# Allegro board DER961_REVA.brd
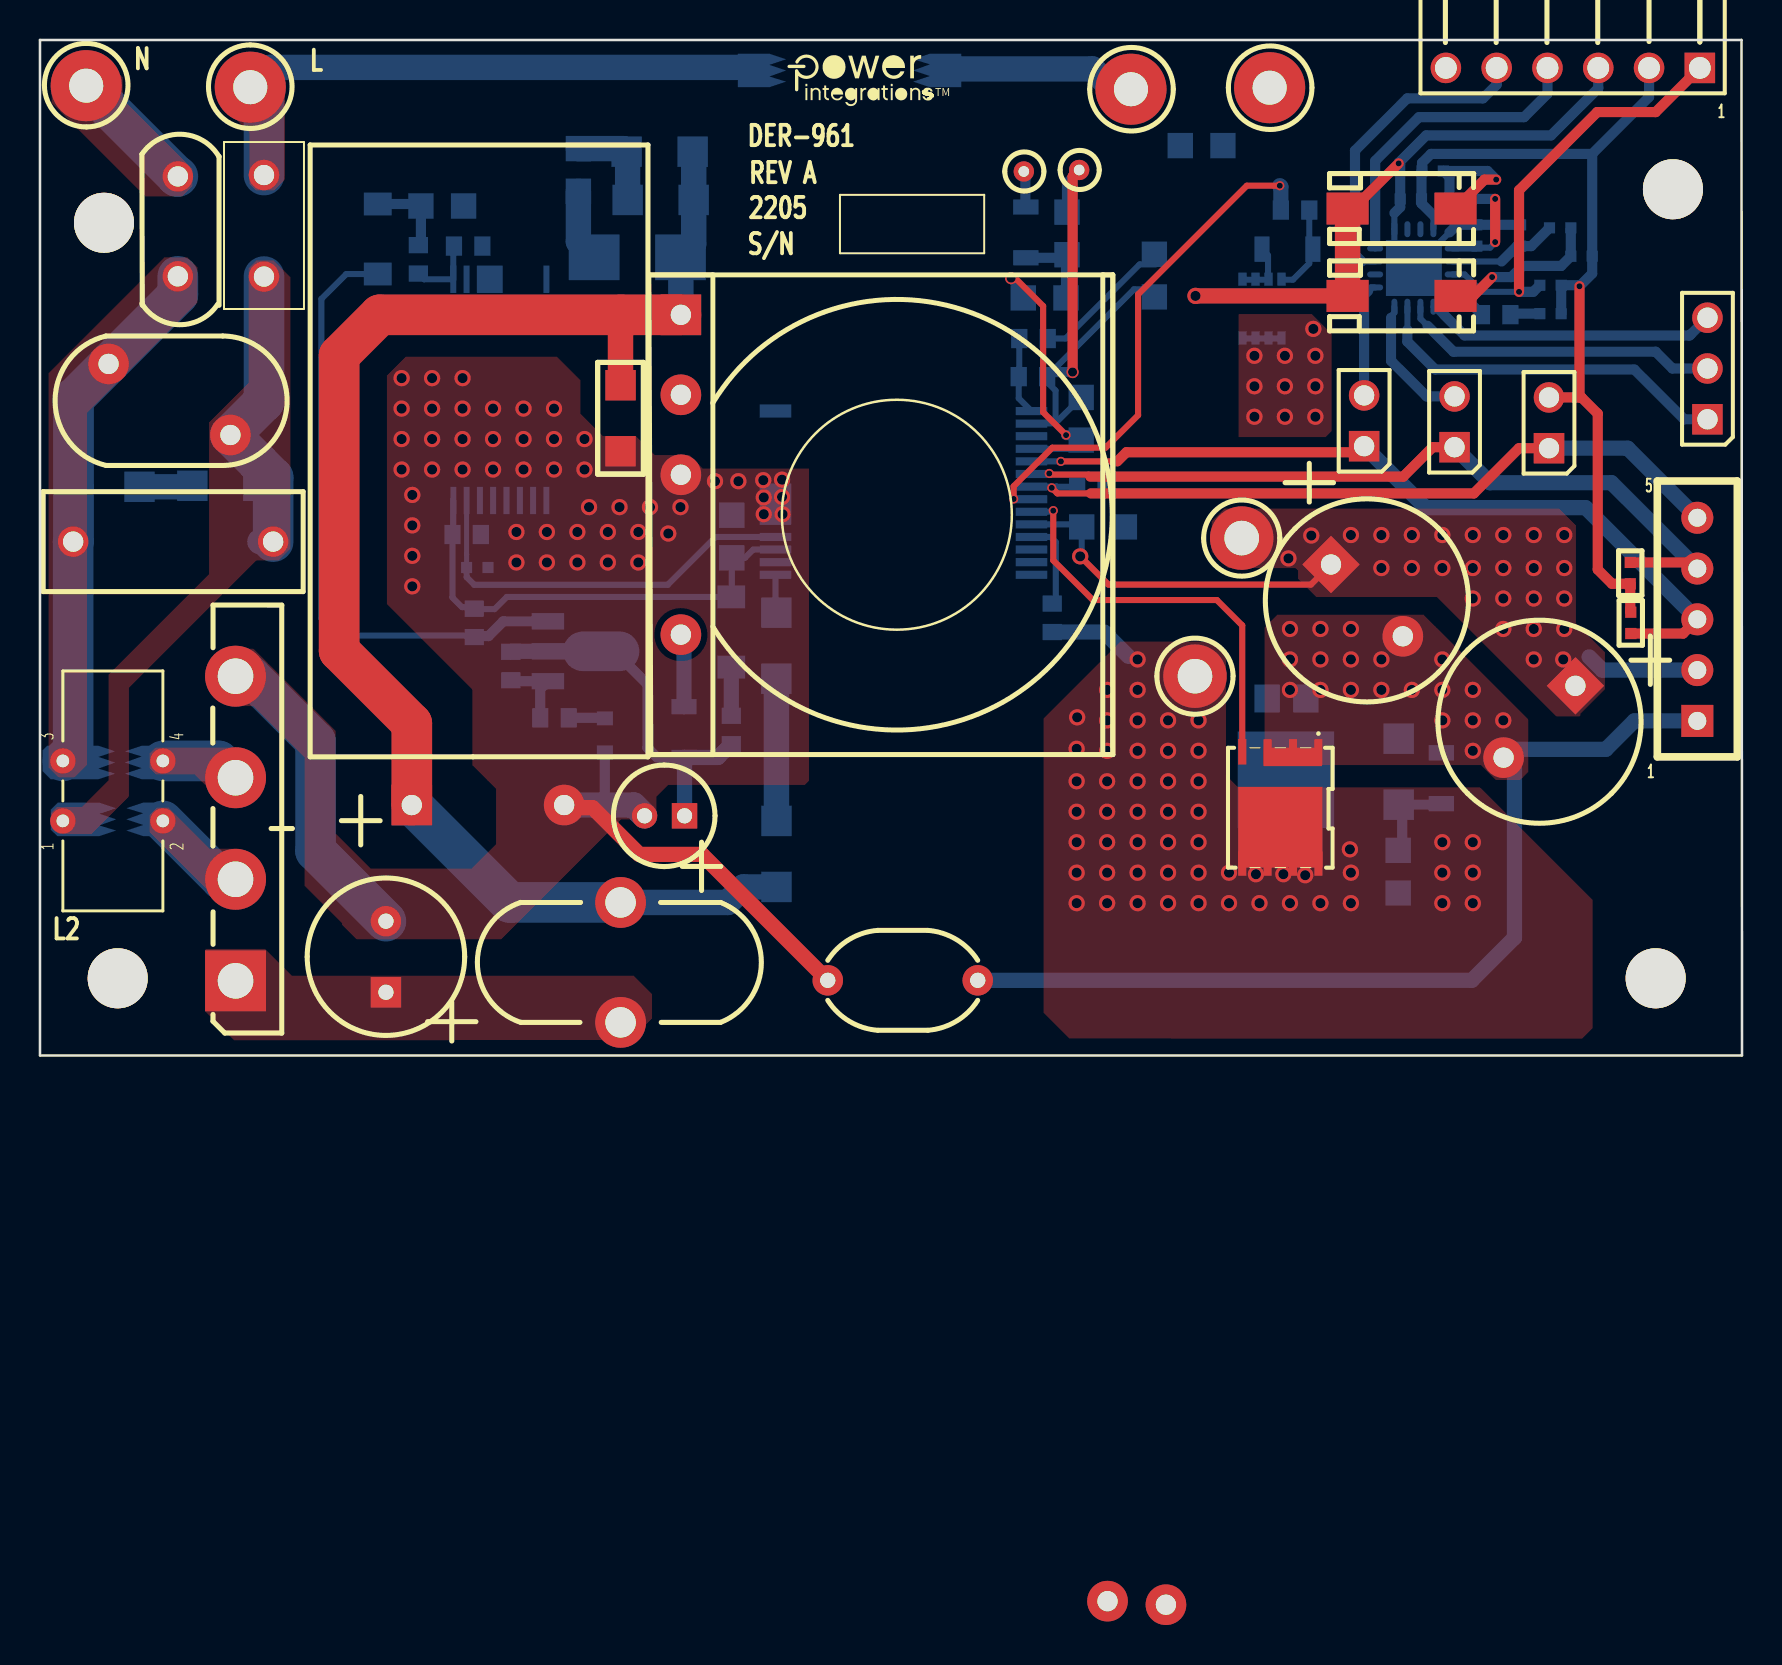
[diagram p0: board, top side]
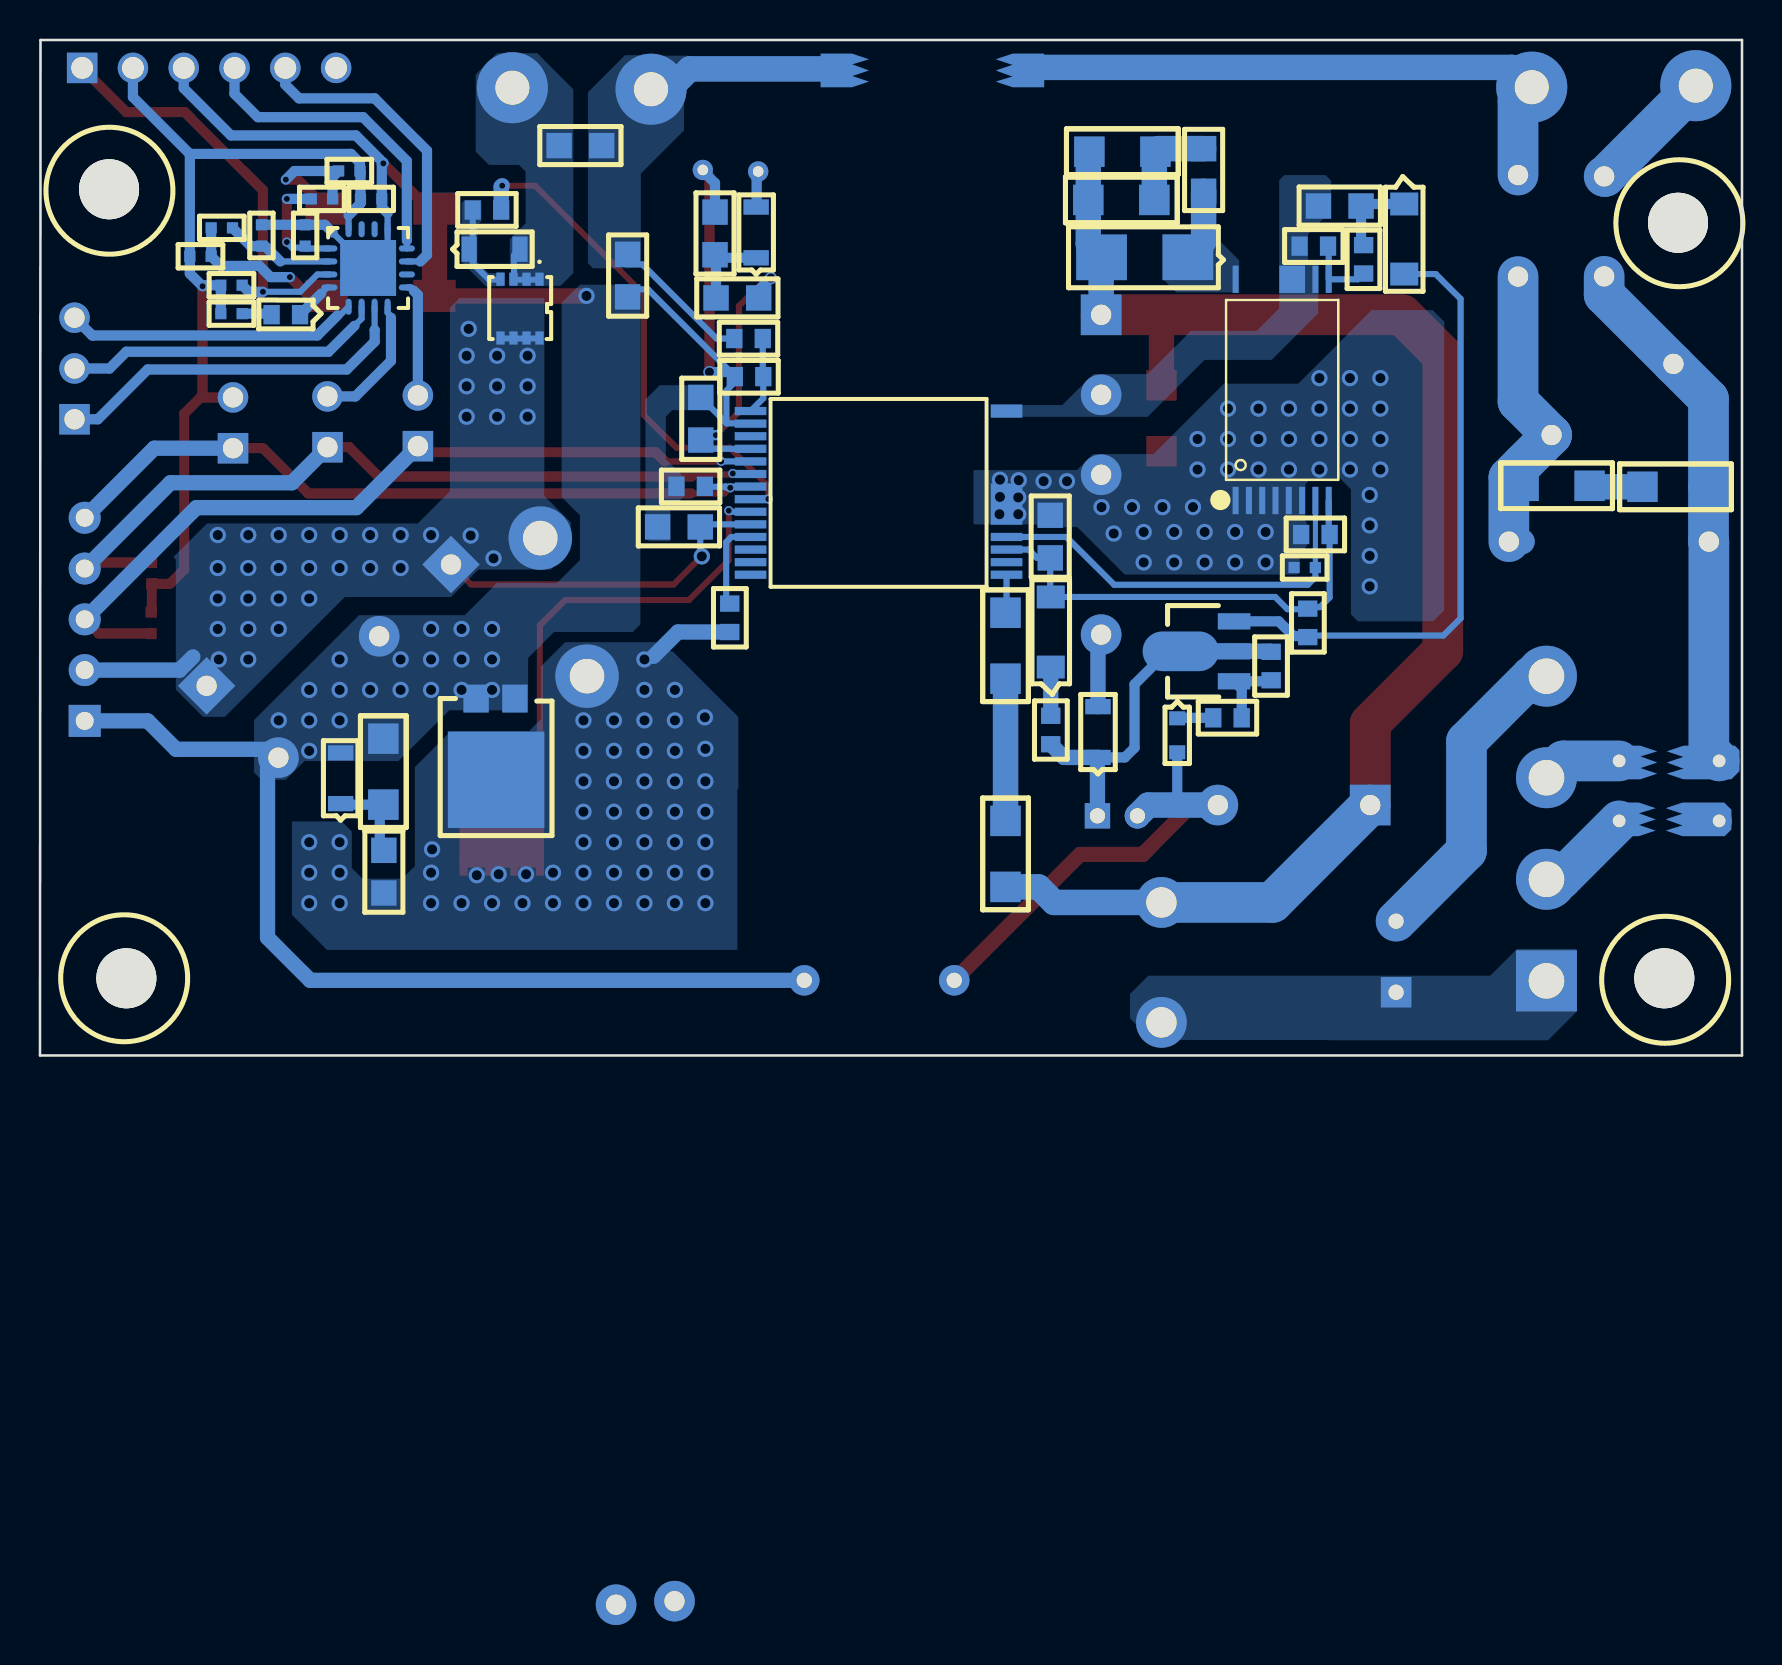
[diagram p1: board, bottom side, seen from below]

Outline 85.12 x 50.8 mm; copper layers: TOP, BOTTOM. Coordinates in mm from the lower left corner of the outline.
Outline path: 0,50.8 0,0 85.12,0 85.09,50.8 0,50.8

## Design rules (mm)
constraint set DEFAULT: min track width 0.508

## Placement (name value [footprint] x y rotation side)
BR1  GBU4K-BP  [PIDAXBRIDGEGBU8]  9.78 3.73 90 top
C1  470 pF  [PINPCAPRAD7P5X11P5LS7P5MM030]  39.4 3.76 0 top
C2  100 nF  [PISMC1206]  32.69 42.8 180 bottom
C3  22 uF  [PIPOLCAPCLYD320LS140030]  17.3 3.16 90 top
C4  100 uF  [PIPOLCAPCLYD630LS300040]  18.59 12.53 0 bottom
C5  2.2 nF  [PISMC1206]  29.03 33.53 270 top
C6  470 uF  [PIPOLCAPCYLD400LS200040]  76.78 18.49 225 top
C7  470 uF  [PIPOLCAPCYLD400LS200040]  64.56 24.56 315 top
C8  1 uF  [PISMC0805]  57.02 45.52 0 bottom
C9  680 pf  [PISMC0805]  67.92 8.13 90 bottom
C10  4.7uF  [PISMC0603]  50.37 33.96 180 bottom
C11  2.2 uF  [PISMC0805]  52.07 30.78 90 bottom
C12  10 uF  [PISMC0805]  51.36 42.19 270 bottom
C13  2.2 uF  [PISMC0805]  54.23 26.44 180 bottom
C14  22 uF  [PIPOLCAPCLYD200LS80030]  32.23 11.99 180 top
C15  2.2 uF  [PISMC0603]  53.29 28.47 180 bottom
C16  100 nF  [PISMC0603]  20.7 40.49 0 bottom
C17  1 uF  [PISMC0805]  21.18 42.49 180 bottom
C18  0.1 uF  [PINPXCAPRAD5X13X11P1MM040]  11.66 25.7 180 top
C19  100 nF  [PISMC0603]  20.62 26.06 0 bottom
C20  0.47 uF  [PISMC0805]  34.59 24.89 90 bottom
C21  1 nF  [PISMR0402]  71.86 40.49 90 bottom
C22  100 nF  [PISMR0402]  68.02 42.85 0 bottom
C23  1 nF  [PISMR0402]  74.04 40.49 90 bottom
C24  100 nF  [PISMC1206]  32.64 45.21 180 bottom
D1  BAV19WS  [PISMSOD323]  63.65 40.34 180 bottom
D2  BAV19WS  [PISMSOD323]  70.08 12.6 90 bottom
D3  V12P12-M3/86A  [PI_SM_D_TO-277A]  63.32 17.86 0 bottom
D4  BAV3004WS-7  [PISMSOD323]  32.21 14.91 90 bottom
D5  BAV19WS  [PISMSOD323]  49.3 39.9 90 bottom
D6  HS1KFL  [PI_SM_SOD-123_12]  16.89 42.6 270 bottom
D7  Green  [PI_SM_D_0603]  72.11 37.06 0 bottom
F1  3.15 A  [PI_RST_MICROFUSE]  11.2 44.04 270 top
FL1  Hole_70mils  [PI_HOLE_70MIL]  60.12 25.88 90 top
FL2  Hole_70mils  [PI_HOLE_70MIL]  57.78 18.97 90 top
FL3  Hole_30mils  [PI_HOLE_30MIL]  49.2 44.22 90 top
FL4  Hole_30mils  [PI_HOLE_30MIL]  51.97 44.3 90 top
J1  CON6  [PI_MOLEX_06_RA_22SERIES]  83.01 49.4 180 bottom
J2  CON2  [PIMOLEX2KKHEADER]  66.22 30.48 90 top
J3  CON5  [PI_HDRF_1X5_HIROSE]  82.88 16.74 90 top
J4  CON2  [PIMOLEX2KKHEADER]  75.46 30.38 90 top
J5  CON3  [PI_MOLEX_3_100_HEADER]  83.39 31.83 90 top
J6  CON2  [PIMOLEX2KKHEADER]  70.74 30.43 90 top
L1  68 uH  [PI2P14DX6MMWD060]  29.03 1.66 90 top
L2  250 uH  [PI_TOROID_CMC4P_V_275UH]  1.14 11.73 90 top
MTG_HOLE1  No 4  [PIMTGHOLE4]  81.66 43.33 0 top
MTG_HOLE2  No 4  [PIMTGHOLE4]  3.89 3.86 0 top
MTG_HOLE3  No 4  [PIMTGHOLE4]  80.8 3.86 0 top
MTG_HOLE4  No 4  [PIMTGHOLE4]  3.2 41.66 0 top
NOREF  -  []  36.83 49.96 0 top
NOREF#2  -  []  -145.5 34.88 0 top
NOREF#3  -  []  0.03 0 0 top
NOREF#4  -  []  0.03 0 90 top
NOREF#5  -  []  -225.3 -132.18 0 top
Q1  2SCR514PHZGT100  [PISMSOT89123]  25.4 18.72 90 bottom
Q2  AON6220  [PISMPQFN5X6B]  63.93 15.19 180 top
Q3  AON7510  [PISM8DFN_EP3P3X3P3A]  61.11 37.36 0 bottom
R1  1.80 M  [PISMR1206]  36.83 11.73 270 bottom
R2  15  [PISMR1206]  67.95 15.85 270 bottom
R3  560  [PISMR0603]  62.05 42.29 0 bottom
R4  1.80 M  [PISMR1206]  36.83 22.15 270 bottom
R5  0.009  [PISMR0805]  55.73 37.95 90 bottom
R6  10  [PISMR0603]  50.39 35.86 180 bottom
R7  47  [PISMR0603]  50.62 21.18 90 bottom
R8  604  [PISMR0805]  49.17 37.9 0 bottom
R9  62 k  [PISMR0603]  23.55 20.19 270 bottom
R10  47  [PISMR0603]  34.57 15.57 90 bottom
R11  NO POP  [PISMR1206]  10.92 28.5 180 bottom
R12  NO POP  [PISMR1206]  4.98 28.45 180 bottom
R13  28.0 k  [PISMR0603]  18.92 40.54 270 bottom
R14  3.3 k  [PISMR0603]  21.72 20.93 90 bottom
R15  10.5 k  [PISMR0603]  25.02 16.89 0 bottom
R16  30 k  [PISMR0402]  22.4 24.41 180 bottom
R17  10 K  [PISMR0402]  75.01 38.53 0 bottom
R18  10 K  [PISMR0402]  70.18 44.25 180 bottom
R19  470  [PISMR0402]  70.48 42.85 0 bottom
R20  10 K  [PISMR0402]  76.56 39.98 0 bottom
R21  470  [PISMR0402]  76.56 41.4 180 bottom
R22  10 K  [PISMR0402]  75.01 37.11 0 bottom
R23  4.70 k  [PISMR0402]  79.55 22.17 270 top
R24  4.70 k  [PISMR0402]  79.53 23.6 90 top
R25  0.0  [PISMR0805]  26.92 43.23 90 bottom
RT1  2.5  [PI_RAD150X300LS200D030]  6.89 38.98 90 top
RV1  300 Vac  [PIDISC350X225LS240X140040]  9.52 31.04 180 top
SW1  EVQ-PE105K  [PI_SWITCH_SPST_SMD_1]  70.79 42.37 180 top
SW2  EVQ-PE105K  [PI_SWITCH_SPST_SMD_1]  70.79 38 180 top
T1  EQ25  [PI_BOBBIN_EQ-25_6P]  42.85 27.05 0 top
TP1  WHT  [PITPKEYSTONE125X125]  10.52 48.44 180 top
TP2  BLK  [PITPKEYSTONE125X125]  2.31 48.51 180 top
TP3  RED  [PITPKEYSTONE125X125]  61.49 48.41 90 top
TP4  GRN  [PITPKEYSTONE125X125]  54.56 48.34 90 top
U1  CPZ1062M  [PI_SM_MINSOP16A_1]  25.32 27.76 180 bottom
U2  INN4375  [INSOP-T28D]  43.18 28.14 180 bottom
U3  PIC16F18325  [PI_SM_16_UQFN_EP]  68.71 39.4 180 bottom
VR1  SMAJ170A-13-F  [PISMDO214AC12]  27.71 39.93 0 bottom
VR2  MMSZ5261BT1G  [PI_SM_SOD-123_12]  34.57 19.43 90 bottom
VR3  BZX58550-C10X  [PISMDSOD52312]  28.24 16.87 270 bottom

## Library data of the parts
BR1 = DISCRETE BRIDGE_+~~-: alternate symbols: (pidaxbridgegbu8_horz); room: 1
C1 C8 C10 C20 = CAP NP: room: 3
C2 C16 C17 C19 C24 = CAP NP: room: 2
C3 = CAP POL: alternate symbols: (pipolcapclyd320ls140d30h750)
C4 = CAP POL: alternate symbols: (pipolcapclyd630ls3000401120h)
C5 = CAP NP: room: 1
C6 C7 = CAP POL: room: 3
C9 C11 C13 = CAP NP
C12 = CAP NP: alternate symbols: (pismc0805_1); room: 3
C14 = CAP POL: alternate symbols: (pipolcapclyd5p0x12p5ls2p0d30h); room: 2
C15 = CAP NP: alternate symbols: (pismc0603_1)
C18 = CAP NP: alternate symbols: (pinpxcaprad5x13x11p1mm040h); room: 1
C21-C23 = CAP NP: alternate symbols: (pismr0402_1)
D1 D2 D5 = DIODE: room: 3
D3 = DIODE SCHOTTKY_TO-277A: room: 3
D4 D6 = DIODE: room: 2
D7 = LED
F1 = FUSE: alternate symbols: (pirstmicrofusehoz); room: 1
FL1-FL4 = FlyingLead: room: 3
J1 = CON6
J2 J4 J6 = CON2
J3 = CON5
J5 = CON3
L1 = INDUCTOR
L2 = TORRID 4P_12_34: alternate symbols: (pi_toroid_CMC4p_V,pi_toroid_CMC4p_V_275uH); room: 1
MTG_HOLE1-MTG_HOLE4 = MTG_HOLE_6-32
Q1 = NPN_BCE
Q2 = FET_N_SGD_123_4_5678: room: 3
Q3 = FET_N_SGD_123_4_1: room: 3
R1 R2 R4 R6 R15 R17-R24 = R
R3 R5 R7 R8 = R: room: 3
R9 R10 R13 R14 R16 = R: room: 2
R11 R12 = R: room: 1
R25 = R: alternate symbols: (pismr0805_1); room: 3
RT1 = THERMISTOR: alternate symbols: (pirad400x300ls200040_h)
RV1 = VARISTOR
SW1 SW2 = SW PUSHBUTTON
T1 = BEQ25_6P
TP1-TP4 = TESTPOINT
U1 = ClampZeroMinSOP16: room: 2
U2 = DEV_INN4375: room: 3
U3 = PIC16F18325-I/JQ
VR1 VR2 = DIODE_ZENER: room: 2
VR3 = DIODE_ZENER: alternate symbols: (pi_sm_d_ssmini2p)

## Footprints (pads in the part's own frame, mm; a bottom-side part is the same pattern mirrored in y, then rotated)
INSOP-T28D
  rect 1.58x0.409 smd: 1(-6.401,4.094) 2(-6.401,3.465) 3(-6.401,2.835) 4(-6.401,2.205) 5(-6.401,1.575) 6(-6.401,0.945) 7(-6.401,0.315) 8(-6.401,-0.315) 9(-6.401,-0.945) 10(-6.401,-1.575) 11(-6.401,-2.205) 12(-6.401,-2.835) 13(-6.401,-3.465) 14(-6.401,-4.094) 15(6.401,-4.094) 16(6.401,-3.465) 17(6.401,-2.835) 18(6.401,-2.205)
  rect 1.58x2.07 smd: 19(6.401,-0.559)
  rect 1.58x0.66 smd: 28(6.401,4.094)
PI2P14DX6MMWD060
  round 2.54 hole 1.524: 1(0,0) 2(5.999,0)
PI_BOBBIN_EQ-25_6P
  rect 2.032x2.032 hole 1.016: 1(-10.8,10)
  round 2.032 hole 1.016: 2(-10.8,5.999) 3(-10.8,1.999) 4(10.536,-54.348) 5(-10.8,-5.999) 6(13.457,-54.526)
PI_HDRF_1X5_HIROSE
  rect 1.6x1.6 hole 0.899: 1(0,0)
  round 1.6 hole 0.899: 2(2.54,0) 3(5.08,0) 4(7.62,0) 5(10.16,0)
PI_HOLE_30MIL
  round 1.016 hole 0.533: 1(0,0)
PI_HOLE_70MIL
  round 3.175 hole 1.727: 1(0,0.025)
PI_MOLEX_3_100_HEADER
  rect 1.524x1.524 hole 1.016: 1(0,0)
  round 1.524 hole 1.016: 2(2.54,0) 3(5.08,0)
PI_MOLEX_06_RA_22SERIES
  rect 1.524x1.524 hole 1.092: 1(0,0)
  round 1.524 hole 1.092: 2(2.54,0) 3(5.08,0) 4(7.62,0) 5(10.16,0) 6(12.7,0)
PI_RAD150X300LS200D030
  round 1.524 hole 1.016: 1(0,0) 2(4.999,0)
PI_RST_MICROFUSE
  round 1.524 hole 1.016: 1(0,0) 2(5.08,0)
PI_SM_16_UQFN_EP
  oval 0.8x0.3 smd: 1(-1.938,0.975) 2(-1.938,0.325) 3(-1.938,-0.325) 4(-1.938,-0.975) 9(1.938,-0.975) 10(1.938,-0.325) 11(1.938,0.325) 12(1.938,0.975)
  oval 0.3x0.8 smd: 5(-0.975,-1.938) 6(-0.325,-1.938) 7(0.325,-1.938) 8(0.975,-1.938) 13(0.975,1.938) 14(0.325,1.938) 15(-0.325,1.938) 16(-0.975,1.938)
  custom 0.7x0.7 smd: EP(0,0)
PI_SM_D_0603
  rect 0.813x0.965 smd: 1(0,0) 2(1.422,0)
PI_SM_D_TO-277A
  rect 1.27x1.397 smd: 1(-0.015,0) 2(-1.956,0)
  rect 4.826x4.826 smd: 3(-1.016,4.064)
PI_SM_MINSOP16A_1
  rect 0.3x1.369 smd: 1(0,0) 2(0.665,0) 3(1.331,0) 4(1.994,0) 5(2.659,0) 6(3.325,0) 7(3.99,0) 8(4.656,0) 9(4.656,11.067) 10(3.99,11.067) 16(0,11.067)
  rect 1.293x1.369 smd: 11(2.83,11.067)
PI_SM_SOD-123_12
  rect 1.143x1.397 smd: 1(0,0) 2(3.505,0)
PI_SWITCH_SPST_SMD_1
  rect 2.108x1.6 smd: 1(0,0) 2(5.4,0)
PI_TOROID_CMC4P_V_275UH
  round 1.27 hole 0.635: 1(0,0) 2(0,-5.001) 3(3,0) 4(3,-5.001)
PIDAXBRIDGEGBU8
  rect 3.048x3.048 hole 1.778: 1(0,0)
  round 3.048 hole 1.778: 2(5.08,0) 3(10.16,0) 4(15.24,0)
PIDISC350X225LS240X140040
  round 2.032 hole 1.016: 1(0,0) 2(6.096,-3.556)
PIMOLEX2KKHEADER
  rect 1.524x1.524 hole 1.016: 1(0,0)
  round 1.524 hole 1.016: 2(2.54,0)
PIMTGHOLE4
  round 3 hole 3: 1(0,0)
PINPCAPRAD7P5X11P5LS7P5MM030
  round 1.524 hole 0.762: 1(0,0) 2(7.501,0)
PINPXCAPRAD5X13X11P1MM040
  round 1.524 hole 1.016: 1(0,0) 2(10,0)
PIPOLCAPCLYD200LS80030
  rect 1.27x1.27 hole 0.762: 1(0,0)
  round 1.27 hole 0.762: 2(1.999,0)
PIPOLCAPCLYD320LS140030
  rect 1.524x1.524 hole 0.762: 1(0,0)
  round 1.524 hole 0.762: 2(3.556,0)
PIPOLCAPCLYD630LS300040
  rect 2.032x2.032 hole 1.016: 1(0,0)
  round 2.032 hole 1.016: 2(7.62,0)
PIPOLCAPCYLD400LS200040
  rect 2.032x2.032 hole 1.016: 1(0,0)
  round 2.032 hole 1.016: 2(5.08,0)
PISM8DFN_EP3P3X3P3A
  rect 0.419x0.66 smd: 1(-0.975,-1.471) 2(-0.325,-1.471) 3(0.325,-1.471) 4(0.975,-1.471) 5(0.975,1.471) 6(0.325,1.471) 7(-0.325,1.471) 8(-0.975,1.471)
PISMC0603
  rect 0.813x0.965 smd: 1(0,0) 2(1.422,0)
PISMC0805
  rect 1.27x1.27 smd: 1(0,0) 2(2.134,0)
PISMC1206
  rect 1.524x1.524 smd: 1(0,0) 2(3.302,0)
PISMDO214AC12
  rect 2.54x2.286 smd: 1(0,0) 2(4.318,0)
PISMDSOD52312
  rect 0.699x0.8 smd: 1(0,0) 2(1.699,0)
PISMPQFN5X6B
  rect 0.406x1.27 smd: 1(0,0) 2(1.27,0) 3(2.54,0) 4(3.81,0)
  rect 0.406x1.219 smd: 5(3.81,5.588) 6(2.54,5.588) 7(1.27,5.588) 8(0,5.588)
PISMR0402
  rect 0.559x0.559 smd: 1(0,0) 2(1.067,0)
PISMR0603
  rect 0.813x0.965 smd: 1(0,0) 2(1.422,0)
PISMR0805
  rect 1.27x1.27 smd: 1(0,0) 2(2.134,0)
PISMR1206
  rect 1.524x1.524 smd: 1(0,0) 2(3.302,0)
PISMSOD323
  rect 0.762x1.27 smd: 1(0,0) 2(2.54,0)
PISMSOT89123
  rect 0.813x1.626 smd: 1(0,0) 3(2.997,0)
  rect 0.813x2.388 smd: 2(1.499,0.381)
PITPKEYSTONE125X125
  round 3.556 hole 1.702: 1(0,0)

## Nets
GND_SIGNAL: C1.2 C6.2 C7.2 C10.1 C11.2 C12.1 C13.1 C15.1 C21.2 C22.1 C23.2 D2.2 D3.1 D3.2 FL4.1 J1.3 J3.1 Q2.1(S) Q2.2 Q2.3 R2.1 R5.1 SW1.2 SW2.2 U2.2 U3.13(VSS) U3.EP
BP: C19.1 C20.1 R14.2 U1.8 U2.17 VR2.2
BPS: C11.1 R8.1 U2.4
D: C9.1 D3.3(CATHODE) FL2.1 Q2.5 Q2.6 Q2.7 Q2.8 R7.1
D1: C6.1 C7.1 C13.2 FL1.1 J3.2 Q3.5 Q3.6 Q3.7 Q3.8 U2.10
HSD: R16.2 U1.7 U2.18
PY_D: C16.2 C17.1 T1.2 U1.10 U1.11 U2.28
PY_S: BR1.4 C1.1 C3.2 C4.2 C5.2 C14.2 C19.2 C20.2 R16.1 T1.3 U1.1 U1.2 U1.3 U1.4 U1.5 U1.6 U2.19 VR3.2
RTN: C8.1 R5.2 R6.1 TP4.1
S1: C8.2 D1.2 Q3.1(S1) Q3.2 Q3.3 TP3.1
SCL: J2.1 J3.3 R23.2 U2.5
SDA: J3.4 J6.1 R24.2 U2.6
SR: Q2.4 U2.9
UVCC: C15.2 J3.5 J4.1 U2.7
V-PIN: R4.1 U2.15
VB/D: R3.1 U2.8
N12382100: C9.2 D2.1 R2.2
N12382458: C14.1 D4.1 Q1.2 R9.1 R10.1
N12382462: D4.2 T1.5
N12382746: Q1.1 R9.2 R15.1
N12382804: R25.1 U1.16 VR1.1
N12382856: R10.2 VR2.1
N12382926: C16.1 R13.2 U1.9
N12382930: D6.2 Q1.3(EMITTER) R14.1
N12383060: C17.2 D6.1 R13.1
N12396349: BR1.1 C3.1 L1.1
N12396391: BR1.3(AC2) L2.4
N12396649: C18.1 F1.2 L2.1 R11.1 RV1.1
N12396657: R11.2 R12.1
N12396665: C18.2 L2.3 R12.2 RT1.1 RV1.2
N12396815: F1.1 TP1.1
N12398163: R1.1 R4.2
N12503104: C12.2 D5.1 R8.2
N12503149: D5.2 FL3.1
N12504243: D1.1 Q3.4 R3.2
N12596211: R7.2 U2.11
N12608133: C10.2 R6.2 U2.1
N12703783: C2.1 C4.1 C5.1 C24.1 L1.2 R1.2 T1.1 VR1.2
N12708941: RT1.2 TP2.1
N12714135: C2.2 C24.2 R25.2
N12716573: BR1.2 L2.2
N12772840: R15.2 VR3.1
N12794080: J1.1 R17.1 U3.3
N12794088: C22.2 J1.2 J4.2 R17.2 R18.2 R20.2 R22.2 R23.1 R24.1 U3.16
N12794144: J1.4 U3.12
N12794152: J1.5 U3.11
N12794212: R18.1 R19.1 SW1.1
N12794224: C21.1 R19.2 U3.1
N12794382: C23.1 R21.2 U3.2
N12794426: D7.1(CATHODE) U3.4
N12794434: J2.2 U3.9
N12794496: J5.3 U3.5
N12794500: J5.2 U3.6
N12794504: J5.1 U3.7
N12794508: J6.2 U3.8
N12794532: R20.1 R21.1 SW2.1
N12794554: D7.2 R22.1

Pads without a net: J1 6; MTG_HOLE1 1; MTG_HOLE2 1; MTG_HOLE3 1; MTG_HOLE4 1; T1 4 6; U2 3 12 13 14 16; U3 10 14 15

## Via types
v1: diameter 0.457, hole 0.305, TOP to BOTTOM, 14 vias
v2: diameter 0.813, hole 0.508, TOP to BOTTOM, 162 vias
v3: diameter 0.61, hole 0.457, TOP to BOTTOM, 2 vias

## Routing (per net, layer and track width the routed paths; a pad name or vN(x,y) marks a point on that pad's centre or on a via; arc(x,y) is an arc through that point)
GND_SIGNAL: length 113.9
  TOP w0.508: v3(51.64,34.19) 51.64,43.97 FL4.1 ; SW1.2 65.68,42.37 v1(67.95,44.63)
  TOP w0.762: SW2.2 v2(57.78,38)
  TOP w1.27: SW1.2 SW2.2
  BOTTOM w0.305: 50.79,31.64 C11.2 52.11,32.88 ; 50.79,31.64 50.77,31.62 49.6,31.62 U2.2 ; 50.79,31.64 50.79,33.26 50.37,33.68 C10.1 ; 55.63,38.33 54.71,38.33 50.57,34.19 ; C15.1 53.29,28.5 ; 70.48,41.17 U3.EP 68.71,39.41 67.73,40.38 U3.13 67.73,42.14
  BOTTOM w0.508: J1.3 77.93,48.39 75.56,46.02 69.32,46.02 67.95,44.65 ; v1(67.95,44.63) 67.95,44.65 ; 67.95,44.65 68.02,44.58 C22.1 68.02,42.43 67.73,42.14 ; 70.48,41.17 70.87,41.55 C21.2 C23.2 ; C12.1 51.36,43.64 51.97,44.25 FL4.1 ; v3(51.64,34.19) 50.57,34.19 50.37,33.99 C10.1
  BOTTOM w0.762: J3.1 79.73,16.74 78.31,15.32 73.61,15.32 73.19,14.9 73.74,14.36 73.74,5.89 71.6,3.76 C1.2
  vias: v2(62.51,21.34) v2(62.51,19.81) v2(62.51,18.29) v2(64.03,21.34) v2(64.03,19.81) v2(64.03,18.29) v2(65.56,21.34) v2(65.56,19.81) v2(65.56,18.29) v2(67.08,19.81) v2(67.08,18.29) v2(68.61,18.29) v2(70.13,19.81) v2(70.13,18.29) v2(70.13,16.76) v2(71.65,18.29) v2(71.65,16.76) v2(71.65,15.24) v2(73.18,16.76)
BP: length 23.6
  BOTTOM w0.305: U1.8 20.67,26.1 C19.1 20.62,22.91 21.11,22.43 21.64,22.43 R14.2 21.74,22.33 22.73,22.33 23.34,22.94 VR2.2 34.59,22.96 C20.1 35.26,24.89 35.67,25.31 U2.17
BPS: length 13.9
  TOP w0.305: v3(48.56,38.89) 48.77,38.89 50.16,37.49 50.16,32.18 v1(51.31,31.03)
  BOTTOM w0.305: U2.4 51.63,30.35 C11.1
  BOTTOM w0.508: C11.1 51.82,31.03 v1(51.31,31.03) ; R8.1 49.17,38.28 v3(48.56,38.89)
D: length 4.3
  BOTTOM w0.762: 54.43,19.96 53.21,21.18 R7.1
  vias: v2(51.87,16.92) v2(51.84,15.34) v2(51.84,13.72) v2(51.84,12.19) v2(51.84,10.67) v2(51.84,9.14) v2(51.84,7.62) v2(53.37,18.29) v2(53.37,16.76) v2(53.37,15.24) v2(53.37,13.72) v2(53.37,12.19) v2(53.37,10.67) v2(53.37,9.14) v2(53.37,7.62) v2(54.89,19.81) v2(54.89,18.29) v2(54.89,16.76) v2(54.89,15.24) v2(54.89,13.72) v2(54.89,12.19) v2(54.89,10.67) v2(54.89,9.14) v2(54.89,7.62) v2(56.41,16.76) v2(56.41,15.24) v2(56.41,13.72) v2(56.41,12.19) v2(56.41,10.67) v2(56.41,9.14) v2(56.41,7.62) v2(57.94,16.76) v2(57.94,15.24) v2(57.94,13.72) v2(57.94,12.19) v2(57.94,10.67) v2(57.94,9.14) v2(57.94,7.62) v2(59.46,9.14) v2(59.46,7.62) v2(60.81,9.07) v2(60.99,7.62) v2(62.18,9.07) v2(62.51,7.62) v2(63.27,9.02) v2(64.03,7.62) v2(65.51,10.31) v2(65.56,9.14) v2(65.56,7.62) v2(70.13,10.67) v2(70.13,9.14) v2(70.13,7.62) v2(71.65,10.67) v2(71.65,9.14) v2(71.65,7.62)
D1: length 25.3
  TOP w0.305: C7.1 63.56,23.56 53.43,23.56 v2(52.02,24.97)
  BOTTOM w0.305: v2(52.02,24.97) 52.1,25.04 C13.2 51.97,26.57 U2.10 ; 60.11,35.87 62.06,35.87 62.03,35.83
  BOTTOM w0.762: 77.47,19.94 78.13,19.28 J3.2
  vias: v2(60.73,35) v2(60.73,33.48) v2(60.73,31.95) v2(62.26,35) v2(62.26,33.48) v2(62.26,31.95) v2(62.43,24.87) v2(63.58,26.01) v2(63.68,36.35) v2(63.78,35) v2(63.78,33.48) v2(63.78,31.95) v2(65.56,26.04) v2(67.08,26.04) v2(67.08,24.38) v2(68.61,26.04) v2(68.61,24.38) v2(70.13,26.04) v2(70.13,24.38) v2(71.65,26.04) v2(71.65,24.38) v2(71.65,22.86) v2(73.18,26.04) v2(73.18,24.38) v2(73.18,22.86) v2(73.18,21.34) v2(74.7,26.04) v2(74.7,24.38) v2(74.7,22.86) v2(74.7,21.34) v2(74.7,19.81) v2(76.17,19.81) v2(76.23,26.04) v2(76.23,24.38) v2(76.23,22.86) v2(76.23,21.34)
HSD: length 20.5
  BOTTOM w0.254: U1.7 21.33,25.07 21.34,25.07 R16.2
  BOTTOM w0.305: R16.2 21.34,23.93 21.72,23.55 31.39,23.55 33.79,25.94 U2.18 36.76,25.96
PY_S: length 39.6
  TOP w0.762: C4.2 26.34,12.4 27.63,12.4 29.97,10.06 33.1,10.06 C1.1
  BOTTOM w0.508: VR3.2 28.24,12.68 28.09,12.53
  BOTTOM w1.27: C14.2 29.7,12.53 C4.2
  BOTTOM w2.032: BR1.4 10.52,18.97 13.78,15.71 13.78,10.24 C3.2
  vias: v2(18.08,33.88) v2(18.08,32.36) v2(18.08,30.84) v2(18.08,29.31) v2(18.62,28.04) v2(18.62,26.52) v2(18.62,24.99) v2(18.62,23.47) v2(19.61,33.88) v2(19.61,32.36) v2(19.61,30.84) v2(19.61,29.31) v2(21.13,33.88) v2(21.13,32.36) v2(21.13,30.84) v2(21.13,29.31) v2(22.66,32.36) v2(22.66,30.84) v2(22.66,29.31) v2(23.83,26.19) v2(23.83,24.66) v2(24.18,32.36) v2(24.18,30.84) v2(24.18,29.31) v2(25.35,26.19) v2(25.35,24.66) v2(25.7,32.36) v2(25.7,30.84) v2(25.7,29.31) v2(26.87,26.19) v2(26.87,24.66) v2(27.23,30.84) v2(27.23,29.31) v2(27.46,27.43) v2(28.4,26.19) v2(28.4,24.66) v2(28.98,27.43) v2(29.92,26.19) v2(29.92,24.66) v2(30.51,27.43) v2(31.42,26.11) v2(32.03,27.43) v2(33.76,28.73) v2(34.92,28.73) v2(36.17,28.78) v2(36.2,27.91) v2(36.2,27.08) v2(37.11,28.8) v2(37.11,27.94) v2(37.13,27.08)
RTN: length 16.6
  BOTTOM w0.305: 55.8,39.57 54.99,39.57 51.28,35.86 R6.1
  BOTTOM w1.27: 45.29,49.35 52.63,49.35 53.64,48.34 TP4.1
S1: length 2.5
  BOTTOM w0.305: 60.11,38.81 61.41,38.81 61.41,40.04
SCL: length 40.8
  TOP w0.305: v1(51.05,29.72) 53.87,29.72
  TOP w0.508: J2.1 65.91,30.18 54.33,30.18 53.87,29.72 ; J3.3 82.17,21.11 R23.2
  BOTTOM w0.305: v1(51.05,29.72) U2.5
  BOTTOM w0.762: J2.1 69.29,27.41 77.29,27.41 J3.3
SDA: length 40
  TOP w0.305: v1(50.47,29.11) 50.53,29.06 52.43,29.06 52.53,28.96
  TOP w0.508: 52.53,28.96 68.17,28.96 69.65,30.43 J6.1 ; J3.4 82.58,24.66 R24.2
  BOTTOM w0.305: v1(50.47,29.11) 50.44,29.09 U2.6
  BOTTOM w0.762: J3.4 78.59,28.65 72.52,28.65 J6.1
SR: length 20.7
  TOP w0.305: Q2.4 60.12,21.51 58.85,22.78 52.65,22.78 50.67,24.77 v1(50.67,27.25)
  BOTTOM w0.305: v1(50.67,27.25) 50.62,27.2 U2.9
UVCC: length 37.3
  TOP w0.305: v1(50.6,28.4) 50.88,28.12 52.55,28.12
  TOP w0.508: 52.55,28.12 71.7,28.12 73.96,30.38 J4.1
  BOTTOM w0.305: 50.84,28.46 50.85,28.45 51.84,28.45 C15.2 ; 50.84,28.46 50.77,28.4 v1(50.6,28.4) ; 50.84,28.46 U2.7
  BOTTOM w0.762: J3.5 79.4,30.38 J4.1
V-PIN: length 1.9
  BOTTOM w0.305: U2.15 36.78,22.2 R4.1
VB/D: length 25.8
  TOP w0.305: v1(48.69,27.84) 48.69,28.47 50.62,30.4 53.29,30.4 54.91,32.03 54.91,38.07 60.35,43.51 v1(62,43.51)
  BOTTOM w0.305: U2.8 48.7,27.83 v1(48.69,27.84)
  BOTTOM w0.762: R3.1 62.05,43.46 v1(62,43.51)
N12382100: length 4.5
  BOTTOM w0.508: 68.12,12.55 68.12,10.46 C9.2 ; 68.12,12.55 R2.2 ; 68.12,12.55 70.03,12.55 D2.1
N12382458: length 18.3
  BOTTOM w0.508: D4.1 30.86,14.91 30.38,15.39 30.38,18.57 28.75,20.19 25.81,20.19 Q1.2
  BOTTOM w0.762: R10.1 33.91,14.91 D4.1 32.23,14.88 C14.1 ; R9.1 23.57,20.22 Q1.2
N12382462: length 3.7
  BOTTOM w0.762: D4.2 32.21,20.89 T1.5
N12382746: length 3.9
  BOTTOM w0.508: R9.2 23.6,18.72 Q1.1 25.02,18.34 R15.1
N12382804: length 3.6
  BOTTOM w1.27: VR1.1 26.92,40.72 R25.1
N12382856: length 2.4
  BOTTOM w0.762: R10.2 VR2.1
N12382926: length 3.5
  BOTTOM w0.305: R13.2 19.21,38.83 U1.9 20.67,40.45 C16.1
N12382930: length 31.4
  BOTTOM w0.305: R14.1 21.64,21.01 14.94,21.01 14.07,21.87 14.07,37.85 15.32,39.09 D6.2
  BOTTOM w0.508: Q1.3 23.16,21.72 22.43,20.98 21.77,20.98 R14.1
N12383060: length 4.3
  BOTTOM w0.305: 18.85,40.54 R13.1
  BOTTOM w0.508: R13.1 19.05,40.67 C17.2 18.95,42.6 D6.1
N12396391: length 4
  BOTTOM w2.032: L2.4 8.94,14.73 BR1.3
N12396649: length 16.6
  BOTTOM w1.27: 10.92,29.64 R11.1 ; C18.1 11,25.7
  BOTTOM w2.032: F1.2 11.2,32.72 RV1.1 11.66,28.91 C18.1
N12396657: length 2.7
  BOTTOM w1.27: R12.1 7.57,28.45 R11.2
N12396665: length 26.6
  BOTTOM w2.032: RT1.1 6.89,38.06 RV1.2 1.68,32.84 R12.2 1.68,25.72 C18.2 1.66,15.25 L2.3
N12396815: length 30.1
  BOTTOM w1.27: 35.56,49.43 11.51,49.43 TP1.1
  BOTTOM w2.032: F1.1 11.2,47.75 TP1.1
N12398163: length 7.1
  BOTTOM w1.27: R1.1 R4.2
N12503104: length 4.5
  BOTTOM w0.508: 51.51,39.9 51.31,39.7 R8.2 ; 51.51,39.9 C12.2 ; 51.51,39.9 D5.1
N12503149: length 1.8
  BOTTOM w0.508: D5.2 49.28,42.47 49.28,43.84 49.2,43.92 FL3.1
N12504243: length 4.7
  BOTTOM w0.305: 63.47,40.51 63.47,39.62 62.66,38.81 62.06,38.81 ; 63.47,40.51 R3.2 ; 63.47,40.51 D1.1
N12596211: length 4.5
  BOTTOM w0.305: U2.11 50.54,25.94 50.8,25.68 50.8,22.78 R7.2
N12608133: length 3.9
  BOTTOM w0.305: R6.2 48.97,33.99 C10.2 48.95,32.87 U2.1
N12703783: length 74.6
  TOP w1.27: 29.06,37.05 29.03,37.03 C5.1
  TOP w2.032: C4.1 18.59,16.61 14.96,20.24 14.96,35.02 17,37.05 T1.1
  BOTTOM w1.27: 32.13,37.13 T1.1 32.05,39.91 VR1.2 32.69,40.59 C2.1 32.69,45.16 C24.1 ; R1.2 35.18,8.43 34.4,7.66 L1.2
  BOTTOM w2.032: L1.2 23.48,7.66 18.61,12.53 C4.1
N12708941: length 6.5
  BOTTOM w2.032: TP2.1 6.85,43.98 RT1.2
N12714135: length 4.9
  BOTTOM w1.27: R25.2 29.18,45.36 C24.2 29.39,45.16 C2.2
N12716573: length 4.8
  BOTTOM w2.032: BR1.2 9.07,8.81 L2.2
N12772840: length 1.8
  BOTTOM w0.508: VR3.1 28.22,16.89 R15.2
N12794080: length 21.5
  TOP w0.508: J1.1 80.8,47.19 77.88,47.19 73.96,43.28 v1(73.96,38.2)
  BOTTOM w0.305: v1(73.96,38.2) 72.11,38.2 71.24,39.07 U3.3
  BOTTOM w0.508: v1(73.96,38.2) 74.68,38.2 R17.1
N12794088: length 49
  TOP w0.508: 76.99,32.92 v1(76.99,38.48) ; 76.99,32.92 77.09,32.92 77.9,32.11 77.9,24.31 78.61,23.6 R24.1 79.53,22.2 R23.1 ; 76.99,32.92 J4.2
  BOTTOM w0.305: R18.2 69.11,42.6 ; 77.62,39.12 77.66,39.15 77.66,39.95 R20.2 ; 69.68,42.03 U3.16
  BOTTOM w0.508: 77.62,45.1 69.56,45.1 69.11,44.65 R18.2 69.09,44.22 C22.2 69.09,42.62 69.68,42.03 ; 77.62,45.1 R20.2 77.62,39.12 v1(76.99,38.48) 76.94,38.53 R17.2 R22.2 ; 77.62,45.1 80.47,47.95 J1.2
N12794144: length 15.7
  BOTTOM w0.305: 66.77,40.77 U3.12
  BOTTOM w0.508: 66.77,40.77 66.77,44.75 68.96,46.94 74.22,46.94 75.39,48.11 J1.4
N12794152: length 15.6
  BOTTOM w0.305: U3.11 66.1,39.72
  BOTTOM w0.508: 66.1,39.72 65.76,40.06 65.76,45.26 68.38,47.88 72.16,47.88 72.85,48.56 J1.5
N12794212: length 7
  TOP w0.508: v1(72.82,43.81) 72.24,43.81 SW1.1
  BOTTOM w0.508: R19.1 70.48,43.94 R18.1 72.39,44.25 v1(72.82,43.81)
N12794224: length 5.8
  TOP w0.508: v1(72.77,42.85) v1(72.77,40.69)
  BOTTOM w0.305: v1(72.77,40.69) 72.77,40.67 72.52,40.41 71.93,40.41 C21.1 71.86,40.41 71.82,40.37 U3.1
  BOTTOM w0.508: R19.2 v1(72.77,42.85)
N12794382: length 5.5
  BOTTOM w0.305: U3.2 73.1,39.72
  BOTTOM w0.508: R21.2 74.57,40.49 C23.1 73.86,40.49 73.1,39.72
N12794426: length 2
  BOTTOM w0.305: 71.06,38.11 70.75,38.42 U3.4
  BOTTOM w0.508: D7.1 71.06,38.11
N12794434: length 5.7
  BOTTOM w0.305: U3.9 66.59,38.42 66.42,38.25
  BOTTOM w0.508: 66.42,38.25 66.22,38.05 J2.2
N12794496: length 14.8
  BOTTOM w0.305: 82.45,36.02 82.51,36.08 82.56,36.08 ; U3.5 70.12,37.02 70.24,37.02
  BOTTOM w0.508: J5.3 82.5,36.02 71.25,36.02 70.24,37.02
N12794500: length 16
  BOTTOM w0.305: U3.6 69.03,36.86 69.39,36.5
  BOTTOM w0.508: J5.2 81.64,34.37 80.8,35.2 70.69,35.2 69.39,36.5
N12794504: length 18.4
  BOTTOM w0.305: U3.7 68.38,36.29
  BOTTOM w0.508: J5.1 82.22,31.83 79.73,34.32 69.77,34.32 68.38,35.71 68.38,36.29 68.38,36.29
N12794508: length 6.7
  BOTTOM w0.305: 67.56,36.91 67.56,36.98 67.73,37.15 U3.8
  BOTTOM w0.508: 67.56,36.91 67.56,34.75 69.34,32.97 J6.2
N12794532: length 8
  TOP w0.508: SW2.1 71.68,38 v1(72.62,38.94)
  BOTTOM w0.508: v1(72.62,38.94) 73.58,38.94 74.14,39.5 76.07,39.5 R20.1 R21.1
N12794554: length 1.5
  BOTTOM w0.508: D7.2 73.58,37.11 R22.1

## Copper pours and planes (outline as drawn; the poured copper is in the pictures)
GND_SIGNAL on TOP (solid shape): 64.11,14.48 61.19,14.48 61.19,15.39 64.11,15.39
GND_SIGNAL on TOP: 61.24,14.53 61.24,21.41 61.87,22.05 69.19,22.05 74.42,16.81 74.42,14.17 74.04,13.79 72.8,13.79 72.06,14.53
GND_SIGNAL on BOTTOM: 51.43,33.53 54.13,33.53 54.84,32.82 54.84,25.91 54.66,25.73 53.59,25.73 53.59,27.28 52.88,27.99 52.88,28.91 53.77,29.79 53.82,29.79 53.82,31.95 53.49,32.28 51.66,32.28 51.43,32.51
GND_SIGNAL on BOTTOM: 59.03,27.94 58.12,27.03 58.12,24.79 59.28,23.62 59.92,23.62 59.94,23.65 62.26,23.65 63.88,22.02 69.16,22.02 74.41,16.78 74.41,14.29 74.42,14.27 74.42,14.17 74.04,13.79 72.82,13.79 71.88,14.73 67.18,14.73 64.64,17.27 60.83,17.27 60.78,17.22 60.71,17.3 60.71,19.89 59.41,21.18 55.47,21.18 55.09,21.56 55.09,38.56 55.55,38.56 55.58,38.53 55.6,38.56 58.12,38.56 59.03,37.64
D on TOP (solid shape): 64.14,9.4 59.92,9.4 59.92,13.44 64.14,13.44
D on TOP: 59.92,13.41 72.01,13.41 77.65,7.77 77.65,1.37 77.11,0.84 56.59,0.84 56.58,0.85 51.47,0.85 50.19,2.13 50.19,16.87 54.03,20.7 58.75,20.7 59.31,20.14 59.31,14.02
D on BOTTOM: 60.68,16.21 64.59,16.21 66.37,14.43 66.37,9.47 67.01,8.84 69.04,8.84 69.04,8.89 69.52,9.37 69.52,11.2 70.03,11.71 72.52,11.71 72.52,7.04 70.76,5.28 50.24,5.28 50.24,13.31 50.19,13.36 50.19,16.93 53.47,20.21 53.56,20.21 54.03,20.68 58.85,20.68 60.05,19.48 60.05,16.84
D1 on TOP: 75.97,27.36 76.81,26.52 76.81,21.62 78.26,20.17 78.26,18.31 77.04,17.09 77.04,17.02 76.99,16.97 75.82,16.97 69.85,22.94 63.83,22.94 62.92,23.85 62.92,24.26 62.79,24.38 59.41,24.38 58.6,25.2 58.6,26.72 59.23,27.36
D1 on TOP: 59.97,37.08 63.6,37.08 64.59,36.09 64.59,31.24 64.29,30.94 59.94,30.94 59.94,37.06
D1 on BOTTOM: 59.89,37.87 64.14,37.87 64.62,37.39 64.62,28.22 66.22,26.62 76.76,26.62 78.45,24.93 78.32,24.8 78.32,18.3 76.96,16.94 75.87,16.94 69.88,22.94 64.57,22.94 63.2,24.31 59.56,24.31 58.57,25.3 58.57,26.67 59.89,27.99
PY_D on BOTTOM: 20.83,44.04 22.89,44.04 23.14,43.79 23.14,37.36 24.24,36.26 27.55,36.26 29.72,34.09 32.44,34.09 33.99,32.54 37.54,32.54 37.54,31.98 37.52,31.95 29.72,31.95 26.87,34.8 23.52,34.8 21.18,37.13 21.18,39.52 21.51,39.52 21.7,39.71 21.7,41.08 20.93,41.86 20.55,41.86 20.55,43.76
PY_S on TOP: 32.47,30.04 33.15,29.36 38.46,29.36 38.46,13.74 38.25,13.54 31.42,13.54 30.82,12.94 30.82,11.84 30.44,11.46 29.87,11.46 29.51,11.81 29.06,11.81 28.96,11.71 28.96,11.38 28.63,11.38 23.06,5.82 15.82,5.82 15.11,6.53 15.11,8 16.46,9.35 21.59,9.35 22.81,10.57 22.81,13.34 21.62,14.53 21.62,18.31 17.35,22.58 17.35,34.01 18.29,34.95 25.86,34.95 27.03,33.78 27.03,32.11 28.14,30.99 29.79,30.99 30.75,30.04
PY_S on TOP: 10.67,20.35 14.78,16.23 14.78,11.1 16.59,9.3 16.59,7.32 15.49,6.22 13.23,8.48 13.23,14.91 10.67,17.48 9.45,17.48 8.76,18.16 8.76,19.61 9.54,20.38 9.58,20.35
PY_S on BOTTOM: 33.25,29.29 38.43,29.29 38.43,26.62 38.38,26.57 35.31,26.57 35.15,26.42 33.86,26.42 33.83,26.44 33.25,26.44 30.86,24.05 22.23,24.05 22.12,24.16 22.12,25.12 21.64,25.6 21.64,26.54 21.84,26.75 21.84,28.57 21.56,28.85 20.09,28.85 19.56,28.32 19.56,22.07 19.2,21.72 15.47,21.72 14.88,22.3 14.88,36.7 15.47,37.29 18.52,37.29 22.2,33.6 25.91,33.6 29.43,30.09 32.45,30.09
RTN on BOTTOM (solid shape): 46.08,48.44 44.5,48.44 43.66,48.72 44.5,49 43.66,49.28 44.5,49.58 43.66,49.83 44.5,50.11 46.08,50.11
RTN on BOTTOM: 54.41,50.04 55.85,50.04 57.71,48.18 57.71,39.62 57.47,39.38 55.56,39.38 55.56,39.4 55.12,39.4 55.07,39.45 55.07,44.12 52.91,46.28 52.91,49.3 52.45,49.76 52.43,49.76 52.68,50.01 54.38,50.01
S1 on BOTTOM: 58.45,48.34 60.25,50.14 62.26,50.14 63.32,49.07 63.32,45.21 62.66,44.55 61.16,44.55 60.83,44.22 60.83,41.63 61.62,40.84 61.62,38.51 59.08,38.51 58.45,39.14
N12382804 on BOTTOM: 25.15,38.18 28.3,38.18 28.96,38.84 28.96,41.05 28.93,41.07 26.44,41.07 25.15,39.78
N12396349 on TOP, BOTTOM: 29.69,3.99 12.6,3.99 11.25,5.33 8.28,5.33 8.28,2.18 9.7,0.76 20.68,0.76 20.69,0.77 29.54,0.77 29.54,0.79 30.61,1.85 30.61,3.07
N12396391 on BOTTOM (solid shape): 6.99,15.11 7.04,15.11 7.04,14.22 6.63,13.82 5.08,13.82 4.24,14.1 5.08,14.38 4.24,14.66 5.08,14.96 4.24,15.21 5.08,15.49 6.6,15.49
N12396391 on TOP: 5.77,15.39 10.11,15.39 11.07,14.43 11.07,13.64 10.22,12.79 9,12.79 7.72,14.07 5.79,14.07 5.49,14.38 5.49,15.11
N12396649 on BOTTOM (solid shape): 3.81,12.37 2.97,12.09 3.81,11.81 2.97,11.51 3.81,11.25 2.97,10.97 0.86,10.97 0.53,11.3 0.53,12.29 0.89,12.65 2.97,12.65
N12396649 on TOP: 10.82,39.78 11.68,39.78 12.52,38.94 12.52,25.35 11.94,24.77 8.61,24.77 8.46,24.92 8.46,31.67 10.44,33.66 10.44,39.4
N12396649 on TOP: 0.84,12.42 2.08,12.42 3.43,13.77 3.43,19.05 8.46,24.08 8.46,25.17 8.48,25.2 10.95,25.2 10.97,25.17 10.97,24.92 4.45,18.39 4.45,12.95 2.57,11.07 0.97,11.07 0.56,11.48 0.56,12.14
N12396665 on BOTTOM (solid shape): 3.76,15.21 2.92,14.94 3.76,14.66 2.92,14.35 3.76,14.1 2.92,13.82 0.53,13.82 0.13,14.22 0.13,15.27 0.36,15.49 2.92,15.49
N12396665 on TOP: 6.22,39.93 7.37,39.93 7.87,39.42 7.87,37.67 2.35,32.14 2.35,14.54 1.73,13.92 0.91,13.92 0.43,14.4 0.43,34.14
N12396815 on BOTTOM (solid shape): 37.31,49.83 36.47,49.56 37.31,49.28 36.47,48.97 37.31,48.72 36.47,48.44 34.9,48.44 34.9,50.11 36.47,50.11
N12396815 on TOP: 10.79,43.28 11.71,43.28 12.24,43.81 12.24,48.84 11.15,49.94 9.73,49.94 9.04,49.25 9.04,47.6 10.46,46.18 10.46,43.61
N12504243 on BOTTOM: 63.07,42.8 63.88,42.8 64.03,42.65 64.03,39.7 62.81,38.48 61.85,38.48 61.85,39.14 62.69,39.14 63.25,39.7 63.25,41.53 63.04,41.73 63.04,42.77
N12708941 on TOP: 4.14,48.92 4.14,47.83 7.62,44.35 7.62,43.48 7.11,42.98 5.26,42.98 0.58,47.65 0.58,48.92 1.5,49.83 3.23,49.83
N12716573 on BOTTOM (solid shape): 7.06,12.14 7.06,10.97 5.16,10.97 4.32,11.25 5.16,11.53 4.32,11.81 5.16,12.12 4.32,12.37 5.16,12.65 6.55,12.65
N12716573 on TOP: 9.93,10.34 8.48,10.34 6.43,12.4 5.84,12.4 5.49,12.04 5.49,11.18 9.07,7.59 10.41,7.59 10.95,8.13 10.95,9.32

Small or netless copper shapes (teardrops, artwork), in the pictures only: 1 on BOTTOM

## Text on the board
Ref Des/Silkscreen Top: L | DER-961 | S/N | 2205 | REV A | N
User.6: FL1,FL2,FL3,FL4 ARE FLYING LEADS FROM TRANSFORMER T1. | PLEASE DELETE THESE PINS | 14.  FAB HOUSE LOGO,DATE CODE TO BE IN SILK SCREEN ONLY.DO NOT USE COPPER. | 13.  MATERIAL FR4 COPPER 2oz THICKNESS 0.062"
User.9: FIGURE | FINISHED_SIZE | 12.0 | 18.0 | 20.0 | 21.0 | 25.0 | 30.0 | 35.4 | 40.0 | 43.0 | 60.0 | 67.0 | 68.0 | 70.0 | 118.1 | DRILL CHART: TOP to BOTTOM | ALL UNITS ARE IN MILS | TOLERANCE_DRILL | +0.0/-0.0 | +3.0/-3.0 | PLATED | QTY | 14 | 2 | 162 | 4 | 6 | 1 | 13 | 5
